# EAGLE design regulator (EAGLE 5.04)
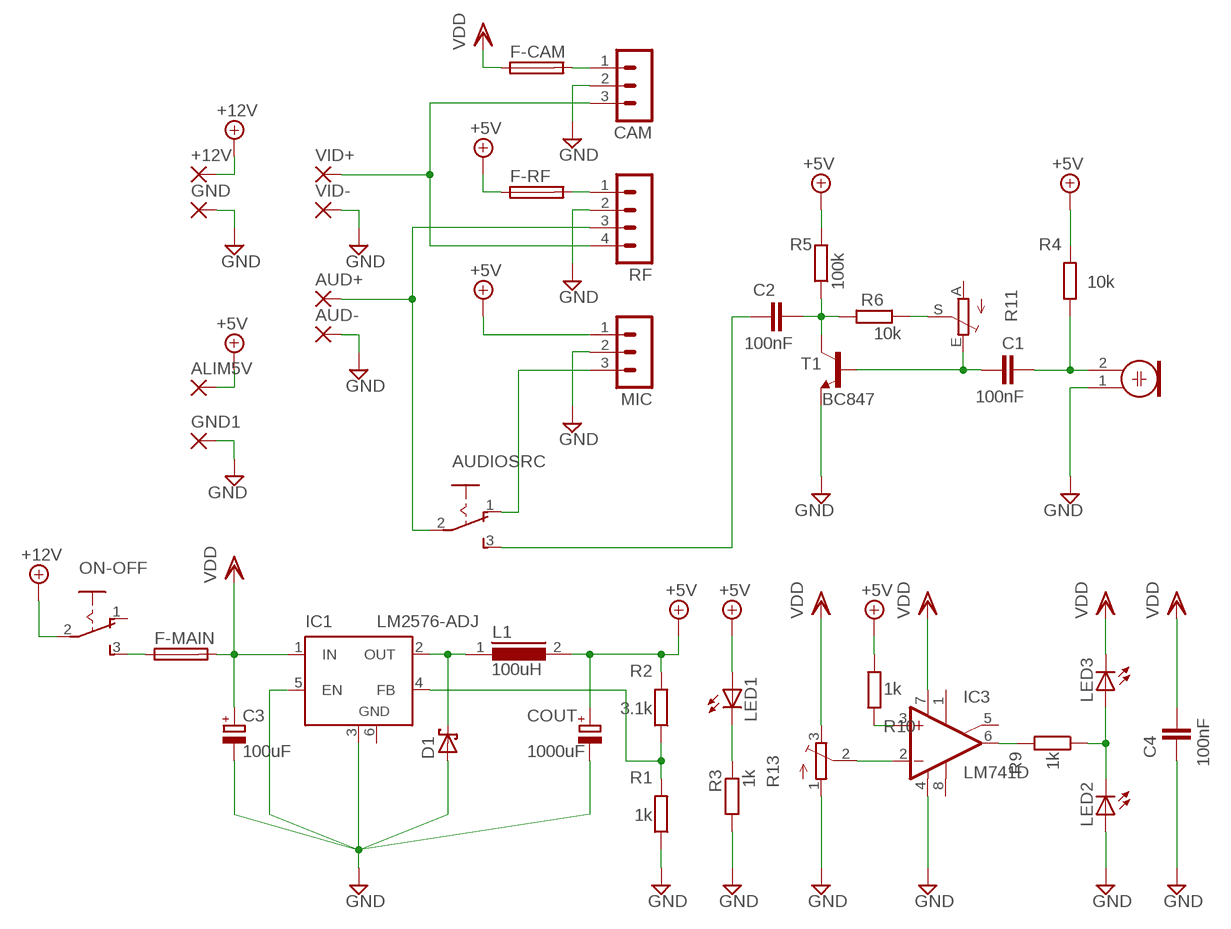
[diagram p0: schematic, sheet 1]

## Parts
+12V  3,81/1,4  [3,81/1,4]
ALIM5V  3,81/1,4  [3,81/1,4]
AUD+  3,81/1,4  [3,81/1,4]
AUD-  3,81/1,4  [3,81/1,4]
AUDIOSRC  255SB  [255SB]
C1  100nF  C-EUC0805  [C0805]
C2  100nF  C-EUC0805  [C0805]
C3  100uF  CPOL-EUE  [PANASONIC_E]
C4  100nF  C-EUC0805  [C0805]
CAM  MA03-1  [MA03-1]
COUT  1000uF  CPOL-EUG  [PANASONIC_G]
D1  SCHOTTKY-DIODESMC  [SMC]
F-CAM  SH22,5  [SH22,5]
F-MAIN  SH22,5  [SH22,5]
F-RF  SH22,5  [SH22,5]
GND  3,81/1,4  [3,81/1,4]
GND1  3,81/1,4  [3,81/1,4]
IC1  LM2576-ADJ  LM2596S  [TO263-5]
IC3  LM741D  [SO08]
L1  100uH  ED22  [ED22]
LED1  LED3MM  [LED3MM]
LED2  LED3MM  [LED3MM]
LED3  LED3MM  [LED3MM]
M1  ELECTRET_MICROPHON-WM-61B  [WM-61B]
MIC  MA03-1  [MA03-1]
ON-OFF  255SB  [255SB]
R1  1k  R-EU_M0805  [M0805]
R2  3.1k  R-EU_M0805  [M0805]
R3  1k  R-EU_M0805  [M0805]
R4  10k  R-EU_0207/7  [0207/7]
R5  100k  R-EU_0207/7  [0207/7]
R6  10k  R-EU_M0805  [M0805]
R9  1k  R-EU_M0805  [M0805]
R10  1k  R-EU_M0805  [M0805]
R11  TRIM_EU-LI10  [LI10]
R13  TRIM_EU-SM-42/43W  [SM-42/43W]
RF  MA04-1  [MA04-1]
T1  BC847  [SOT23]
VID+  3,81/1,4  [3,81/1,4]
VID-  3,81/1,4  [3,81/1,4]

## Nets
+5V: ALIM5V.1(P) COUT.+ F-RF.1 L1.2 LED1.A MIC.1 R2.2 R4.2 R5.2 R10.1
+12V: +12V.1(P) ON-OFF.2(P)
GND: AUD-.1(P) C3.- C4.2 CAM.2 COUT.- D1.A GND1.1(P) GND.1(P) IC1.3(GND) IC1.5(EN) IC3.4(V-) LED2.A M1.1 MIC.2 R1.1 R3.2 R13.1(A) RF.2 T1.2(E) VID-.1(P)
N$1: F-MAIN.1 ON-OFF.3(S)
N$2: D1.C IC1.2(OUT) L1.1
N$3: IC1.4(FB) R1.2 R2.1
N$4: CAM.1 F-CAM.2
N$5: LED1.K(C) R3.1
N$6: AUD+.1(P) AUDIOSRC.2(P) RF.3
N$7: AUDIOSRC.1(O) MIC.3
N$8: F-RF.2 RF.1
N$9: C1.1 M1.2 R4.1
N$10: CAM.3 RF.4 VID+.1(P)
N$11: C1.2 R11.E T1.1(B)
N$12: R6.1 R11.S
N$13: AUDIOSRC.3(S) C2.2
N$14: C2.1 R5.1 R6.2 T1.3(C)
N$15: IC3.2(-IN) R13.2(S)
N$16: IC3.6(OUT) R9.2
N$17: LED2.K(C) LED3.A R9.1
N$18: IC3.3(+IN) R10.2
VDD: C3.+ C4.1 F-CAM.1 F-MAIN.2 IC1.1(IN) IC3.7(V+) LED3.K(C) R13.3(E)
Unconnected: IC3.1(ON1) IC3.5(ON2) IC3.8(OPT) ON-OFF.1(O) R11.A

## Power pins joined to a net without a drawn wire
GND: IC1.6(GND)

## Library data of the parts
+12V ALIM5V AUD+ AUD- GND GND1 VID+ VID- = wirepad:3,81/1,4: THROUGH-HOLE PAD
AUDIOSRC ON-OFF = switch:255SB: SLIDING SWITCH Distributor Buerklin, 11G810
C1 C2 C4 = rcl:C-EU: CAPACITOR, European symbol
C3 COUT = rcl:CPOL-EU: POLARIZED CAPACITOR, European symbol
CAM MIC = con-lstb:MA03-1: PIN HEADER
D1 = diode:SCHOTTKY-DIODE: Schottky Diode
F-CAM F-MAIN F-RF = fuse:SH22,5: FUSE HOLDER
IC1 = linear:LM2596S: STEP-DOWN VOLTAGE REGULATOR
IC3 = linear:*741: OP AMP
L1 = inductors:ED22: INDUCTOR
LED1-LED3 = led:LED: LED
M1 = microphon:ELECTRET_MICROPHON-: Electret Condenser Microphone
R1-R6 R9 R10 = rcl:R-EU_: RESISTOR, European symbol
R11 R13 = pot:TRIM_EU-: POTENTIOMETER
RF = con-lstb:MA04-1: PIN HEADER
T1 = transistor:BC847: NPN TRANSISTOR

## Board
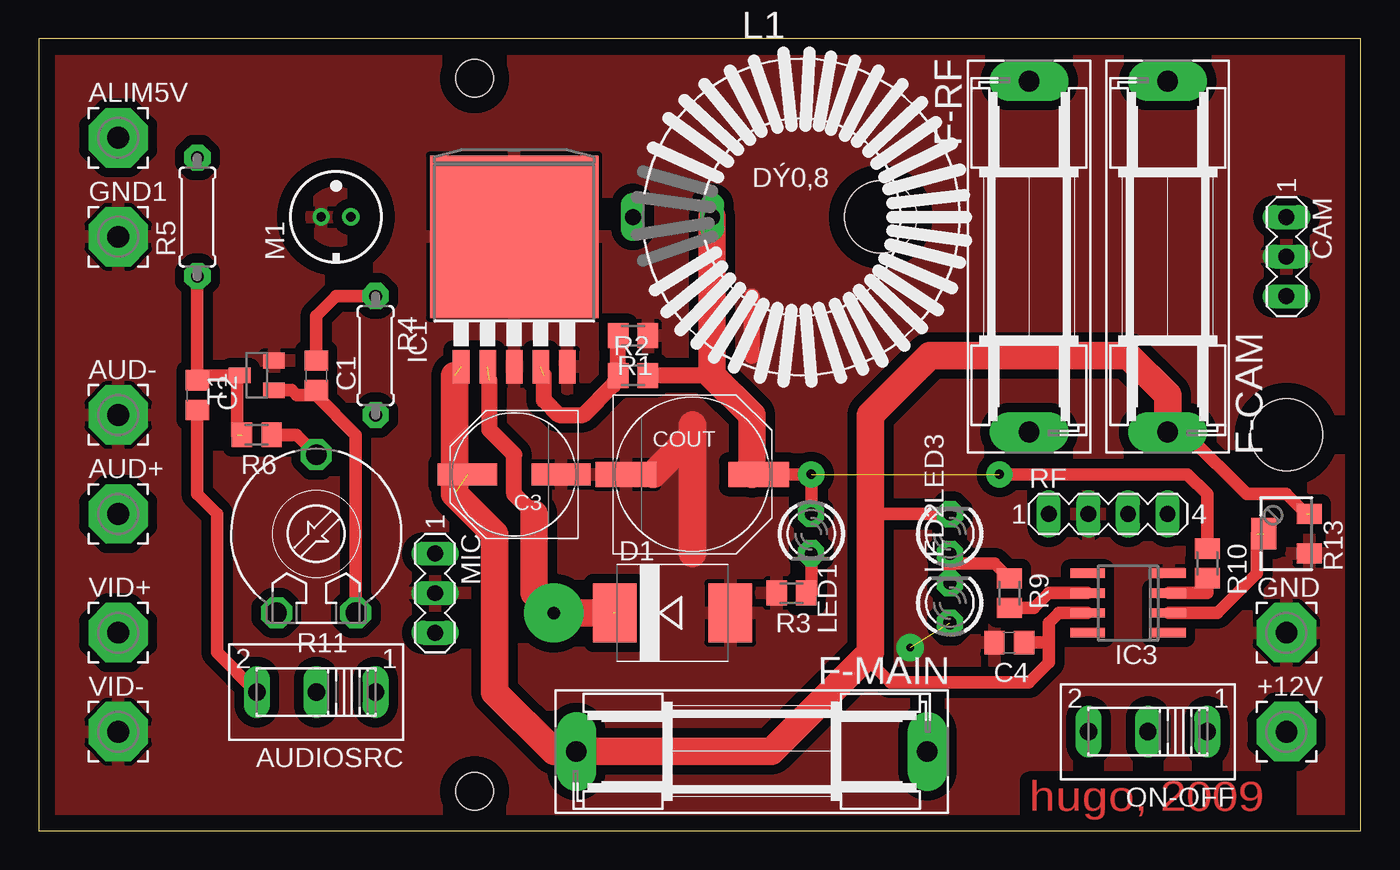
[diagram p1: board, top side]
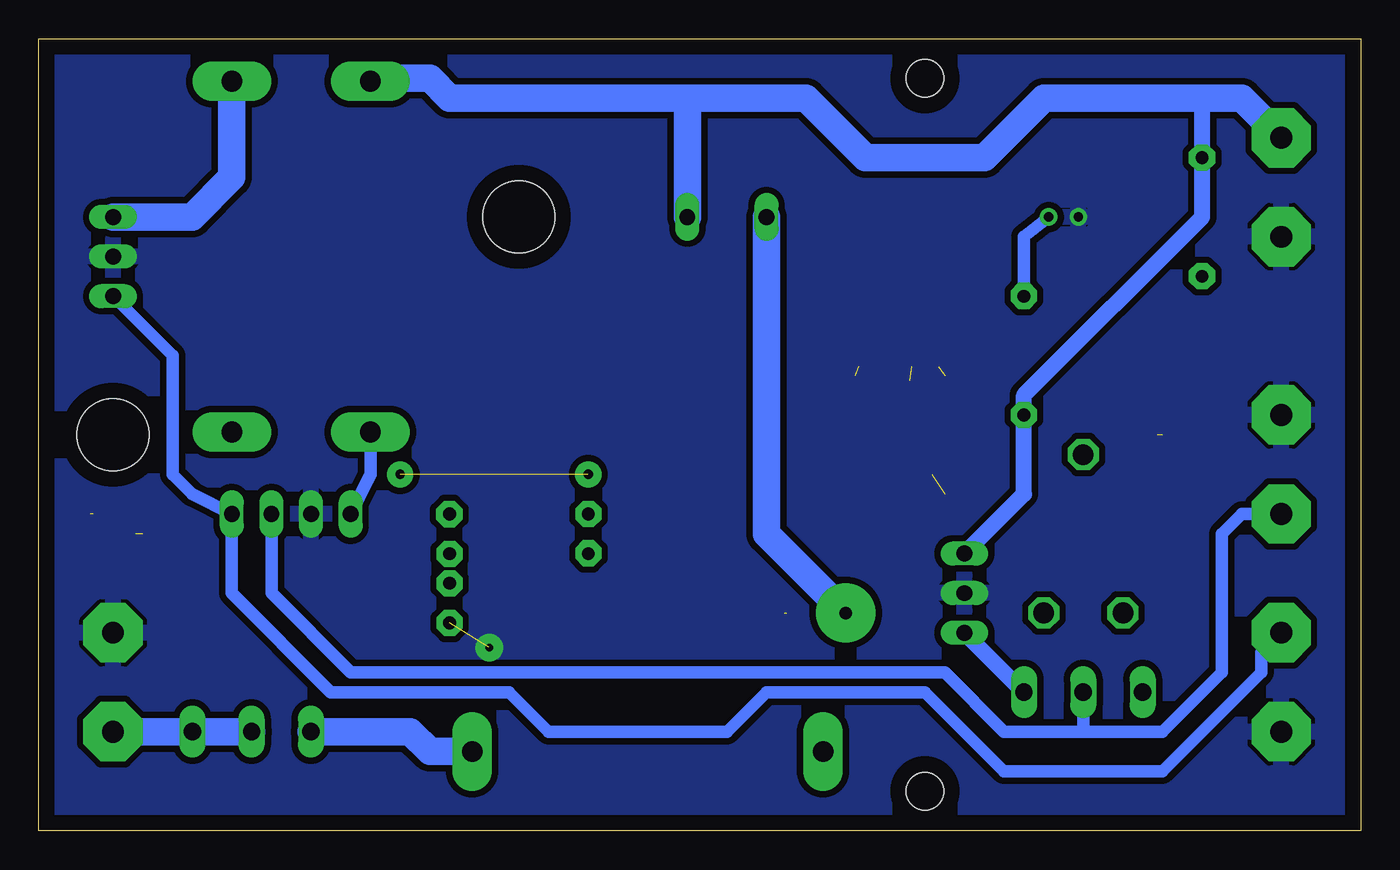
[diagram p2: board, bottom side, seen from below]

Size 84.76 x 50.79 mm. Coordinates in mm from the lower left corner, seen from the top.
Outline: 0,0 84.76,0 84.76,50.79 0,50.79 0,0
Copper layers (1*16): Top 0.035mm / dielectric 1.5mm / Bottom 0.035mm
Design rules "default": minimum track width 10mil, minimum drill 24mil, track to track 8mil, track to pad 8mil, pad to pad 8mil, via to via 8mil, smd to smd 8mil, copper to edge 40mil, drill to drill 8mil, minimum pad ring 10mil, minimum via ring 8mil, stop-mask expansion 4mil, vias tented up to drill 0mil, thermal gap 10mil
Holes 4.6 mm at 80.01,25.4 53.98,39.37
Holes 2.4 mm at 27.94,48.26 27.94,2.54

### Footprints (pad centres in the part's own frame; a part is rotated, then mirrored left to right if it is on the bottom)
3,81/1,4 = drill 1.397 pad 3.81 octagon: 1 0,0
255SB = drill 1.118 long: 1 -3.81,0; 2 0,0; 3 3.81,0
C0805 = smd 1.3 x 1.5: 1 -0.95,0; 2 0.95,0
PANASONIC_E = smd 3.8 x 1.4: + 3,0; - -3,0
MA03-1 = drill 1.016 long: 1 -2.54,0; 2 0,0; 3 2.54,0
PANASONIC_G = smd 3.9 x 1.6: + 4.25,0; - -4.25,0
SMC = smd 2.8 x 3.8: A 3.7,0; C -3.7,0
SH22,5 = drill 1.321 pad 2.54 long: 1 -11.252,0; 2 11.252,0
TO263-5 = smd 1.067 x 2.159: 1 -3.404,-5.791; 2 -1.702,-5.791; 3 0,-5.791; 4 1.702,-5.791; 5 3.404,-5.791 | smd 10.8 x 10.41: 6 0,2.54
SO08 = smd 0.6 x 2.2: 1 -1.905,-2.6; 2 -0.635,-2.6; 3 0.635,-2.6; 4 1.905,-2.6; 5 1.905,2.6; 6 0.635,2.6; 7 -0.635,2.6; 8 -1.905,2.6
ED22 = drill 1.016 long: 1 -10.795,0; 2 -5.715,0
LED3MM = drill 0.813 octagon: A -1.27,0; K 1.27,0
WM-61B = drill 0.6 pad 1 round: 1 0,0.95; 2 0,-0.95
M0805 = smd 1.3 x 1.6: 1 -0.95,0; 2 0.95,0
0207/7 = drill 0.813 octagon: 1 -3.81,0; 2 3.81,0
LI10 = drill 1.321 octagon: A -2.54,-5.08; E 2.54,-5.08; S 0,5.08
SM-42/43W = smd 1.3 x 1.6: 1 -1.27,-1.45; 3 1.27,-1.45 | smd 2 x 1.6: 2 0,1.45
MA04-1 = drill 1.016 long: 1 -3.81,0; 2 -1.27,0; 3 1.27,0; 4 3.81,0
SOT23 = smd 1 x 1.4: 1 -0.95,-1.1; 2 0.95,-1.1; 3 0,1.1

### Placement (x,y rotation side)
+12V  80.01,6.35 0 top
ALIM5V  5.08,44.45 0 top
AUD+  5.08,20.32 0 top
AUD-  5.08,26.67 0 top
AUDIOSRC  17.78,8.89 180 top
C1  17.78,29.21 270 top
C2  10.16,27.94 270 top
C3  30.48,22.86 180 top
C4  62.23,12.06 180 top
CAM  80.01,36.83 270 top
COUT  41.91,22.86 0 top
D1  40.64,13.97 0 top
F-CAM  72.39,36.83 90 top
F-MAIN  45.72,5.08 180 top
F-RF  63.5,36.83 270 top
GND  80.01,12.7 0 top
GND1  5.08,38.1 0 top
IC1  30.48,35.56 0 top
IC3  69.85,14.61 90 top
L1  48.9,39.37 0 top
LED1  49.53,19.05 270 top
LED2  58.42,14.61 90 top
LED3  58.42,19.05 90 top
M1  19.05,39.37 90 top
MIC  25.4,15.24 270 top
ON-OFF  71.12,6.35 180 top
R1  38.1,31.75 180 top
R2  38.1,29.21 0 top
R3  48.26,15.24 180 top
R4  21.59,30.48 270 top
R5  10.16,39.37 90 top
R6  13.97,25.4 180 top
R9  62.23,15.24 270 top
R10  74.93,17.14 270 top
R11  17.78,19.05 0 top
R13  80.01,19.05 90 top
RF  68.58,20.32 0 top
T1  13.97,29.21 90 top
VID+  5.08,12.7 0 top
VID-  5.08,6.35 0 top

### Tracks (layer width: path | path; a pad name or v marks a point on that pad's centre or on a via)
+5V  (via drill 0.6 pad 1.68)  (1 unrouted)
  Top 0.813: COUT.+ v49.53,22.86 LED1.A | R10.1 74.61,18.09 74.93,18.41 74.93,21.59 73.66,22.86 v61.59,22.86
  Top 1.016: 43.18,29.21 R2.2 | 45.72,22.86 COUT.+
  Top 1.778: L1.2 43.18,29.21 45.72,26.67 45.72,22.86
  Bottom 1.016: 10.16,46.99 R5.2 10.16,39.37 21.59,27.94 R4.2 v21.59,26.66 21.59,21.59 MIC.1
  Bottom 1.778: ALIM5V.1 7.62,46.99 10.16,46.99 20.32,46.99 24.13,43.18 31.75,43.18 35.56,46.99 43.18,46.99 | 43.18,46.99 L1.2 | 43.18,46.99 58.42,46.99 59.69,48.26 62.23,48.26 F-RF.1
+12V
  Bottom 1.778: ON-OFF.2 +12V.1
GND  (via drill 0.5 pad 1.78)  (1 unrouted)
  Top 1.016: 45.72,30.48 45.72,34.29
  Top 1.778: 41.91,25.4 39.37,22.86 | 41.91,17.78 41.91,25.4 | 41.91,25.4 41.91,26.04
  other vias: 55.88,11.75
  pour Bottom (isolate 0.406): 1.27,49.53 83.82,49.53 83.82,1.27 1.27,1.27
  pour Top (isolate 0.61): 1.27,49.53 83.82,49.53 83.82,1.27 1.27,1.27
N$1
  Bottom 1.778: F-MAIN.1 59.69,5.08 60.96,6.35 ON-OFF.3
N$2  (via drill 0.8 pad 3.81)  (2 unrouted)
  Top 1.016: 31.75,20.32 30.48,21.59 30.48,24.13 28.89,25.72 28.89,28.89
  Top 1.778: 36.83,13.97 v33.02,13.97 31.75,15.24 31.75,20.32
  Bottom 1.778: v33.02,13.97 38.1,19.05 L1.1
N$3  (1 unrouted)
  Top 1.016: 32.38,29.21 32.38,27.62 33.34,26.67 34.92,26.67 36.83,28.57 R2.1 R1.2
N$4
  Bottom 1.778: F-CAM.2 72.39,41.91 74.93,39.37 CAM.1
N$5
  Top 0.813: R3.1 49.53,15.24 LED1.K
N$6
  Bottom 0.813: AUD+.1 7.62,20.32 8.89,19.05 8.89,10.16 12.7,6.35 17.78,6.35 | RF.3 69.85,15.24 64.77,10.16 26.67,10.16 22.86,6.35 17.78,6.35 | 17.78,6.35 AUDIOSRC.2
N$7
  Bottom 1.016: AUDIOSRC.1 MIC.3
N$8
  Bottom 0.813: RF.1 63.5,22.86 F-RF.2
N$9  (via drill 0.6 pad 1.68)
  Top 0.813: C1.1 17.78,33.02 19.05,34.29 R4.1
  Bottom 0.813: M1.2 21.59,38.1 v21.59,34.31 R4.1
N$10
  Bottom 0.813: CAM.3 76.2,30.48 76.2,22.86 74.93,21.59 RF.4 72.39,15.24 66.04,8.89 54.61,8.89 52.07,6.35 40.64,6.35 38.1,8.89 27.94,8.89 22.86,3.81 12.7,3.81 6.35,10.16 6.35,11.43 VID+.1
N$11
  Top 0.813: 17.78,27.94 C1.2 | 17.78,27.94 20.32,25.4 R11.E | T1.1 16.19,28.26 16.51,27.94 17.78,27.94
N$12
  Top 0.813: R6.1 16.51,25.4 R11.S
N$13
  Top 0.813: C2.2 10.16,21.59 11.43,20.32 11.43,11.43 AUDIOSRC.3
N$14  (1 unrouted)
  Top 0.813: 10.16,29.21 R5.1 | C2.1 10.16,29.21 | 10.16,29.21 12.7,29.21 | 12.7,29.21 T1.3 | 12.7,29.21 12.7,25.4
N$15  (1 unrouted)
  Top 0.813: IC3.2 75.56,13.97 78.11,16.51 78.11,19.05
N$16
  Top 0.813: R9.2 63.82,14.29 64.77,15.24 IC3.6
N$17
  Top 0.813: 58.42,17.14 LED3.A | LED2.K 58.42,17.14 | 58.42,17.14 61.27,17.14 R9.1
N$18
  Top 0.813: IC3.3 74.93,15.24 R10.2
N$19  (via drill 0.6 pad 1.68)
  other vias: 10.17,43.19
N$20  (via drill 0.6 pad 1.68)
  other vias: 10.17,35.57
N$21  (via drill 0.6 pad 1.68)
  other vias: 58.43,13.33
N$22  (via drill 0.6 pad 1.68)
  other vias: 58.43,15.87
N$23  (via drill 0.6 pad 1.68)
  other vias: 58.43,17.75
N$24  (via drill 0.6 pad 1.68)
  other vias: 58.44,20.31
N$25  (via drill 0.6 pad 1.68)
  other vias: 49.52,17.8
N$26  (via drill 0.6 pad 1.68)
  other vias: 49.52,20.31
VDD  (3 unrouted)
  Top 0.813: 53.34,11.43 53.34,10.79 54.61,9.53 63.5,9.53 64.77,10.79 64.77,12.06 | 64.77,12.06 64.77,13.34 65.41,13.97 IC3.7 | 53.34,20.32 LED3.K | F-CAM.1 72.39,25.4 73.66,25.4 77.47,21.59 80.01,21.59 81.28,20.32 | 64.77,12.06 C4.1
  Top 1.778: 26.67,29.21 26.67,21.59 29.21,19.05 29.21,8.89 33.02,5.08 F-MAIN.2 46.99,5.08 53.34,11.43 53.34,20.32 53.34,26.67 57.15,30.48 69.85,30.48 72.39,27.94 F-CAM.1

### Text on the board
Top: hugo, 2009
